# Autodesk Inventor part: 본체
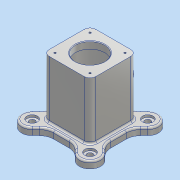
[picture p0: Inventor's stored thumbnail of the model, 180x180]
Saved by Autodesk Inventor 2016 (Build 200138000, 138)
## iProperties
Created: 2019-11
Part Number: 본체
Material: 알루미늄 6061
Document SubType Name: Modeling
Designer: user
Density: 2.7 g/cm^3
Appearance: 알루미늄 - 평지
Mass: 1076.28 g
Surface Area: 879.96 cm^2
Volume: 398.62 cm^3
Author: user
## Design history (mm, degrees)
sketch "스케치2"
  geometry: L1 (-49, 49)-(49, 49); L2 (49, 49)-(49, -49); L3 (49, -49)-(-49, -49); L4 (-49, -49)-(-49, 49); L5 (-49, 49)-(49, -49); L6 (49, 49)-(-49, -49); L7 (49.497, -49.497)-(-49.497, 49.497); L8 (62.225, -36.77)-(-36.77, 62.225); L9 (-62.225, 36.77)-(36.77, -62.225); L10 (-49.497, -49.497)-(49.497, 49.497); L11 (-36.77, -62.225)-(62.225, 36.77); L12 (36.77, 62.225)-(-62.225, -36.77); A1 r 70 centre (0, 0) between (-49.497, 49.497) and (49.497, 49.497); A2 r 18 centre (49.497, -49.497) between (36.77, -62.225) and (62.225, -36.77); A3 r 18 centre (-49.497, 49.497) between (-36.77, 62.225) and (-62.225, 36.77); A4 r 18 centre (-49.497, -49.497) between (-62.225, -36.77) and (-36.77, -62.225); A5 r 18 centre (49.497, 49.497) between (62.225, 36.77) and (36.77, 62.225); 1 further point
  constraints: 28 end point, 10 point on circle, 8 tangent, 5 centre point, 4 midpoint, 4 parallel, 2 point on line, 1 coincident, 1 horizontal, 1 perpendicular
  dimensions: "d5" = 98 distance of L1.start L1.end; "d6" = 98 distance of L3.end L1.start; "d7" = 140 diameter of A1; "d8" = 36 diameter of A3; "d9" = 36 diameter of A5
extrude "돌출1" new body sketch "스케치2" distance "d10" = 12; taper "d11" = 0 deg
sketch "스케치3"
  geometry: L1 (-40, 40)-(40, 40); L2 (40, 40)-(40, -40); L3 (40, -40)-(-40, -40); L4 (-40, -40)-(-40, 40); L5 (-40, 40)-(40, -40); L6 (40, 40)-(-40, -40); 1 further point
  constraints: 12 end point, 2 midpoint, 2 parallel, 1 horizontal, 1 perpendicular
  dimensions: "d12" = 80 distance of L1.start L1.end; "d13" = 80 distance of L3.end L1.start
extrude "돌출2" join sketch "스케치3" distance "d14" = 98; taper "d15" = 0 deg
sketch "스케치4"
  geometry: A1 r 18 centre (-49.497, 49.497) between (-36.77, 62.225) and (-62.225, 36.77) reference; 2 further points
  constraints: 1 coincident
hole "구멍1" sketch "스케치4" at (-49.497, 49.497) diameter "d16" = 10; stored, may be unused: countersink angle "d20" = 90 deg, drill point angle "d22" = 118 deg; dims "d17" = 6, "d18" = 18, "d19" = 4, "d21" = 8
sketch "스케치5"
  geometry: A1 r 18 centre (49.497, 49.497) between (62.225, 36.77) and (36.77, 62.225) reference; A2 r 18 centre (49.497, -49.497) between (36.77, -62.225) and (62.225, -36.77) reference; A3 r 18 centre (-49.497, -49.497) between (-62.225, -36.77) and (-36.77, -62.225) reference; 4 further points
  constraints: 3 coincident
hole "구멍2" sketch "스케치5" at (49.497, 49.497), (49.497, -49.497), (-49.497, -49.497) diameter "d23" = 10; stored, may be unused: countersink angle "d27" = 90 deg, drill point angle "d29" = 118 deg; dims "d24" = 6, "d25" = 18, "d26" = 4, "d28" = 8
sketch "스케치6"
  geometry: C1 r 25 at (0, 0); 1 further point
  constraints: 1 centre point, 1 coincident
  dimensions: "d30" = 50 diameter of C1
extrude "돌출3" cut sketch "스케치6" distance "d31" = 225.75; taper "d32" = 0 deg
node "작업 평면1"
sketch "스케치7"
  geometry: C1 r 35 at (0, 0); 1 further point
  constraints: 1 centre point, 1 coincident
  dimensions: "d34" = 70 diameter of C1
extrude "돌출4" cut sketch "스케치7" distance "d35" = 86; taper "d36" = 0 deg
node "작업 평면2"
sketch "스케치8"
  geometry: C1 r 20 at (0, 61); 1 further point
  constraints: 1 centre point, 1 vertical alignment
  dimensions: "d38" = 61 distance of point (0, 0) C1.centre; "d39" = 40 diameter of C1
extrude "돌출5" join sketch "스케치8" stored distance "d40" = 86; taper "d41" = 0 deg
sketch "스케치9"
  geometry: C1 r 20 at (0, 0) reference; 2 further points
  constraints: 2 coincident
hole "구멍3" sketch "스케치9" at (0, 0) diameter "d42" = 25; stored, may be unused: countersink angle "d46" = 90 deg, drill point angle "d48" = 118 deg; dims "d43" = 6, "d44" = 30, "d45" = 8, "d47" = 55
sketch "스케치10"
  geometry: L1 (-30, 30)-(30, 30); L2 (30, 30)-(30, -30); L3 (30, -30)-(-30, -30); L4 (-30, -30)-(-30, 30); L5 (-30, 30)-(30, -30); L6 (30, 30)-(-30, -30); C1 r 5 at (-49.497, 49.497) reference; A1 r 18 centre (-49.497, 49.497) between (-36.77, 62.225) and (-62.225, 36.77) reference; 5 further points
  constraints: 12 end point, 4 coincident, 2 midpoint, 2 parallel, 1 horizontal, 1 perpendicular
  dimensions: "d49" = 60 distance of L1.start L1.end; "d50" = 60 distance of L1.end L2.end
hole "구멍4" sketch "스케치10" at (-30, 30), (30, 30), (30, -30), (-30, -30) diameter "d51" = 3.242; stored, may be unused: countersink angle "d55" = 90 deg, drill point angle "d57" = 118 deg; dims "d52" = 8, "d53" = 30, "d54" = 8, "d56" = 10
node "작업 평면3"
fillet "모깎기1" dims "d59" = 25
fillet "모깎기2" dims "d60" = 10
fillet "모깎기3" dims "d61" = 3
fillet "모깎기4" dims "d62" = 3
chamfer "모따기1" distance "d63" = 1; stored, may be unused: second distance "d64" = 2, angle "d65" = 45 deg
fillet "모깎기5" dims "d66" = 3
chamfer "모따기2" distance "d67" = 1; stored, may be unused: second distance "d68" = 2, angle "d69" = 45 deg
fillet "모깎기6" dims "d70" = 3
chamfer "모따기3" distance "d71" = 1; stored, may be unused: second distance "d72" = 2, angle "d73" = 45 deg
sketch "스케치11"
  geometry: L1 (60, 0)-(0, 0) reference; L2 (16.811, 110)-(43.189, 110) reference; 3 further points
  constraints: 1 midpoint, 1 vertical alignment, 1 other
  dimensions: "d74" = 10 distance from line of L1 point (30, 10)
feature "엠보싱1" sketch "스케치11" dims "d5" = 98, "d6" = 98, "d7" = 140, "d8" = 36, "d9" = 36, "d75" = 0.5, "d76" = 0
node "솔리드1"
mirror "대칭1"
other parameters: "d33" = 12, "d37" = 55, "d58" = 55
